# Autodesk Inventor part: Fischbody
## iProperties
Shininess: 64.0
Length Units: 11269
Angle Units: 11279
Time Units: 11290
Mass Units: 11283
Length Display Precision: 2
Angle Display Precision: 1
Compacted: True
Part Number: Fischbody
Document SubType Name: Modeling
Created: 2004-02
Material: Standard
Designer: Sec
Manufacturer: Standard
Standards Organization: Custom
Density: 0.0
Volumn: 0.0
Area: 0.0
PropertySet Name: Model Information
Control State: 0
Master: False
Checked Out: False
Author: Sec
